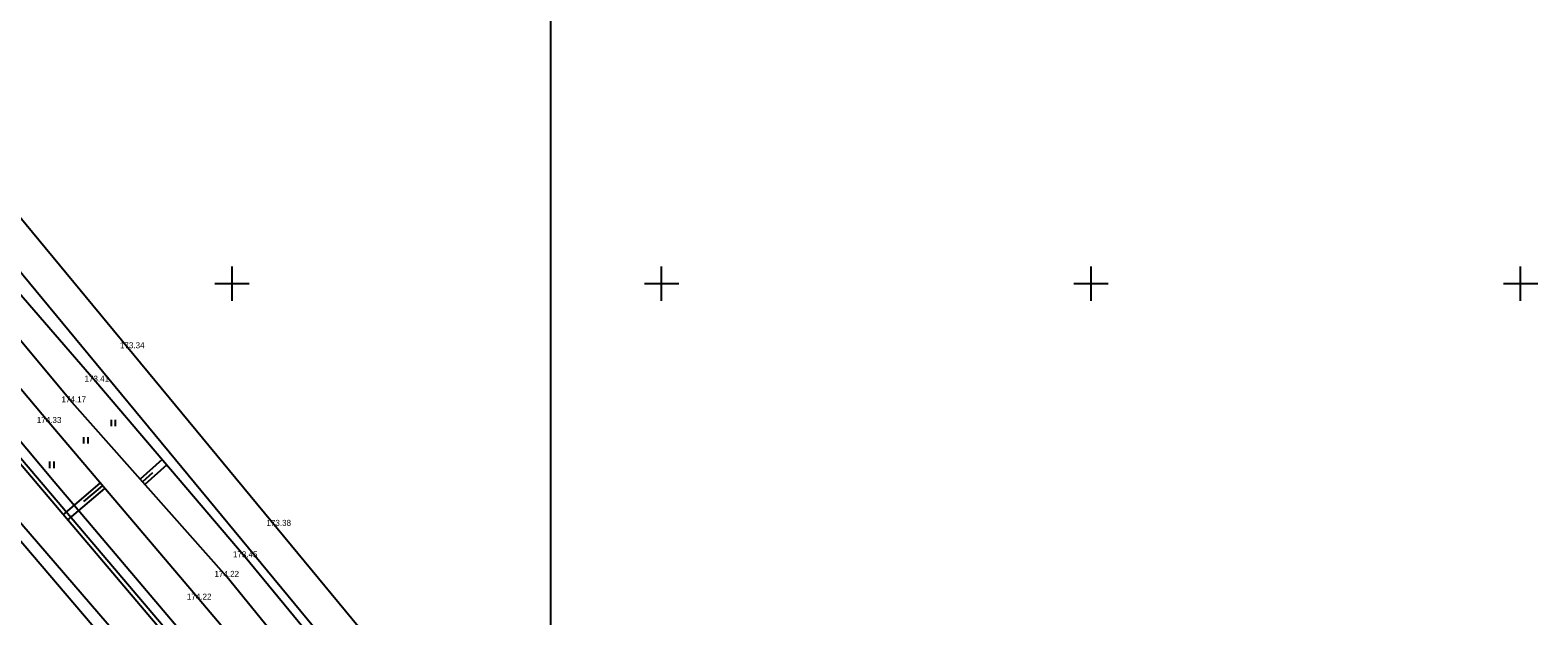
# Model space of a CAD drawing. Extents: x -612546 to -611926, y -1201932 to -1200444.
# Drawn here: x -612123.5 to -611948, y -1201138.7 to -1201070.5 of the extents above; entities that cross this region are included whole.
import ezdxf

# ---------------------------------------------------------------- set-up
doc = ezdxf.new("R2010")
doc.units = 0
for name, color, linetype in [('14 hrana pata svahu', 7, 'Continuous'), ('15 šrafy', 7, 'Continuous'), ('61 legenda křížky', 7, 'Continuous'), ('Hranice parcel', 7, 'Continuous'), ('Vnitřní kresba', 7, 'Continuous'), ('Vrstva 36', 7, 'Continuous'), ('Vrstva 63', 7, 'Continuous'), ('výška bodu', 7, 'Continuous')]:
    doc.layers.add(name, color=color, linetype=linetype)

msp = doc.modelspace()

# ---------------------------------------------------------------- linework, layer by layer
at = {"layer": '14 hrana pata svahu'}
for points in [[(-612115.84, -1201111.42), (-612142.3, -1201080.92), (-612162.58, -1201054.92), (-612187.22, -1201025.94), (-612211.45, -1200996.73), (-612237.71, -1200968.13), (-612275.47, -1200925.26), (-612297.25, -1200898.18), (-612305.42, -1200888.34), (-612310.59, -1200874.11), (-612323.74, -1200837.38), (-612336.44, -1200801.43), (-612350.12, -1200764.09), (-612361.57, -1200731.35), (-612377.95, -1200692.77), (-612388.38, -1200663.69), (-612401.66, -1200625.89), (-612414.44, -1200590.59), (-612427.78, -1200553.92), (-612436.33, -1200532.1), (-612442.76, -1200519.02), (-612455.83, -1200502.43), (-612463.71, -1200487.36), (-612471.87, -1200478.15)], [(-612103.83, -1201136.8), (-612121.3, -1201116.23), (-612147.17, -1201085.43), (-612168.95, -1201059.31), (-612192.84, -1201031.05), (-612217.78, -1201001.78), (-612242.41, -1200972.81), (-612279.4, -1200929.44), (-612302.66, -1200902.78), (-612311.18, -1200891.48), (-612317.69, -1200875.87), (-612330.64, -1200840.25), (-612343.46, -1200803.61), (-612356.83, -1200766.41), (-612369.51, -1200733.46), (-612383.93, -1200694.82), (-612394.68, -1200665.1), (-612407.78, -1200627.56), (-612420.74, -1200592.57), (-612433.93, -1200555.79), (-612441.34, -1200534.1), (-612447.31, -1200522.04), (-612459.97, -1200505.78), (-612472.95, -1200489.44)], [(-612100.62, -1201134.15), (-612118.63, -1201113.83), (-612144.42, -1201082.96), (-612165.7, -1201057.43), (-612190.2, -1201028.76), (-612215.18, -1200999.78), (-612240.07, -1200970.53), (-612277.47, -1200927.11), (-612299.67, -1200900.56), (-612307.52, -1200889.81), (-612314.18, -1200875.11), (-612327.34, -1200838.97)], [(-612083.4, -1201170.96), (-612107.88, -1201140.83), (-612125.72, -1201119.76), (-612151.16, -1201088.66), (-612173.22, -1201063.29), (-612197.5, -1201034.61), (-612222.4, -1201005.63), (-612247.09, -1200977.25), (-612284.99, -1200933.95), (-612307.37, -1200907.39), (-612317.17, -1200894.63), (-612323.51, -1200877.98), (-612336.33, -1200841.94)], [(-612058.08, -1201162.38), (-612067.26, -1201168.1), (-612074, -1201161.58), (-612098.47, -1201131.87), (-612115.84, -1201111.42)], [(-612058.08, -1201162.38), (-612067.19, -1201172.6), (-612076.18, -1201164.21), (-612100.62, -1201134.15)], [(-612070, -1201175.34), (-612078.58, -1201166.64), (-612103.83, -1201136.8)]]:
    msp.add_lwpolyline(points, dxfattribs=at)
at = {"layer": '15 šrafy'}
for p, q in [((-612108.13, -1201120.5), (-612110.7, -1201122.78)), ((-612107.61, -1201121.11), (-612110.17, -1201123.38)), ((-612109.26, -1201122.03), (-612110.43, -1201123.08)), ((-612119.66, -1201126.92), (-612115.34, -1201123.25)), ((-612119.14, -1201127.53), (-612114.82, -1201123.86)), ((-612117.24, -1201125.38), (-612115.08, -1201123.55))]:
    msp.add_line(p, q, dxfattribs=at)
at = {"layer": '61 legenda křížky'}
for p, q in [((-612100, -1201102), (-612100, -1201098)), ((-612050, -1201102), (-612050, -1201098)), ((-612000, -1201102), (-612000, -1201098)), ((-611950, -1201102), (-611950, -1201098)), ((-612102, -1201100), (-612098, -1201100)), ((-612052, -1201100), (-612048, -1201100)), ((-612002, -1201100), (-611998, -1201100)), ((-611952, -1201100), (-611948, -1201100))]:
    msp.add_line(p, q, dxfattribs=at)
at = {"layer": 'Hranice parcel'}
for points in [[(-612492.54, -1200475.45), (-612489.15, -1200479.9), (-612487.29, -1200482.34), (-612470.55, -1200499.86), (-612454.58, -1200517.89), (-612449.12, -1200526.98), (-612444.88, -1200537.01), (-612400.71, -1200658.68), (-612382.76, -1200708.97), (-612320.94, -1200880.21), (-612316.28, -1200891.06), (-612307.37, -1200903.62), (-612259.67, -1200958.71), (-612214.29, -1201012.03), (-612172.62, -1201060.98), (-612120.7, -1201123.05), (-612073.85, -1201178.4), (-612068.4, -1201184.83), (-612055.42, -1201199.11), (-612044.78, -1201213.9), (-612040.42, -1201224.33), (-612036.87, -1201232.26)], [(-612053.63, -1201234.04), (-612049.72, -1201229.74), (-612051.31, -1201220.57), (-612058.28, -1201208.42), (-612073.89, -1201189.58), (-612079.31, -1201183.16), (-612173.25, -1201072.99), (-612266.53, -1200963.98), (-612308.11, -1200916.05), (-612320.05, -1200901.46), (-612326.37, -1200888.91), (-612352.76, -1200817.26), (-612383.45, -1200732.24), (-612424.46, -1200618.96), (-612450.75, -1200547.77), (-612455.75, -1200534.91), (-612462.05, -1200524.68), (-612490.01, -1200492.58), (-612497.19, -1200482.99)], [(-612367.63, -1200702.46), (-612366.44, -1200717.27), (-612308.59, -1200877.88), (-612303.27, -1200888.65), (-612292.69, -1200901.79), (-612203.37, -1201003.51), (-612163.72, -1201050.75), (-612139.89, -1201080.24), (-612084.23, -1201147.54), (-612068.31, -1201163.86)], [(-612027.25, -1201146.78), (-612057.59, -1201153.91), (-612067.61, -1201153.97), (-612081.25, -1201144.86), (-612136.79, -1201077.71), (-612160.63, -1201048.21), (-612200.33, -1201000.9), (-612214.59, -1200984.67)]]:
    msp.add_lwpolyline(points, dxfattribs=at)
at = {"layer": 'Vnitřní kresba'}
msp.add_line((-612174.91, -1201061.11), (-612079.46, -1201173.47), dxfattribs=at)
msp.add_lwpolyline([(-612077.99, -1201182.01), (-612172.2, -1201072.72), (-612264.55, -1200963.36), (-612306.48, -1200914.97), (-612319.15, -1200900.26), (-612324.5, -1200887.86), (-612350.35, -1200818.69), (-612381.6, -1200731.97), (-612422.84, -1200618.87), (-612449.81, -1200544.11), (-612465.28, -1200517.45), (-612482.79, -1200495.64), (-612497.19, -1200482.99)], dxfattribs=at)
at = {"layer": 'Vrstva 36'}
for p, q in [((-612114.05, -1201116.61), (-612114.05, -1201115.86)), ((-612113.55, -1201116.61), (-612113.55, -1201115.86)), ((-612117.25, -1201118.62), (-612117.25, -1201117.87)), ((-612116.75, -1201118.62), (-612116.75, -1201117.87)), ((-612121.2, -1201121.48), (-612121.2, -1201120.73)), ((-612120.7, -1201121.48), (-612120.7, -1201120.73))]:
    msp.add_line(p, q, dxfattribs=at)
at = {"layer": 'Vrstva 63'}
msp.add_line((-612062.93, -1200831.26), (-612062.93, -1201251.26), dxfattribs=at)

# ---------------------------------------------------------------- texts
at = {"layer": 'výška bodu'}
for s, p in [('173.34', (-612113.05, -1201107.53)), ('173.41', (-612117.18, -1201111.42)), ('174.17', (-612119.86, -1201113.83)), ('174.33', (-612122.73, -1201116.23)), ('173.38', (-612096, -1201128.21)), ('173.45', (-612099.9, -1201131.87)), ('174.22', (-612102.05, -1201134.15)), ('174.22', (-612105.26, -1201136.8))]:
    msp.add_text(s, height=0.7, dxfattribs=at).set_placement(p)

doc.saveas('drawing.dxf')
